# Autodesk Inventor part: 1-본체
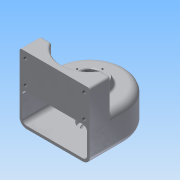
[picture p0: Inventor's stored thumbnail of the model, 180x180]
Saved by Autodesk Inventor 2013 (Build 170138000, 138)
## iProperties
Created: 2015-02
Part Number: 1-본체
Material: 알루미늄 6061
Document SubType Name: Modeling
Designer: Administrator
Density: 2.40731 g/cm^3
Mass: 511.236 g
Surface Area: 706.788 cm^2
Volume: 212.368 cm^3
Author: Administrator
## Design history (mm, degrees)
sketch "스케치1"
  geometry: L1 (-50, 0)-(-50, -50); L2 (-50, -50)-(50, -50); L3 (50, -50)-(50, 0); A1 r 50 centre (0, 0) between (50, 0) and (-50, 0); 1 further point
  constraints: 6 end point, 2 perpendicular, 2 point on circle, 2 tangent, 1 centre point, 1 coincident, 1 horizontal
  dimensions: "d0" = 50 radius of A1; "d2" = 50 distance from line of L2 point (0, 0)
extrude "돌출1" new body sketch "스케치1" distance "d3" = 50; taper "d4" = 0 deg
fillet "모깎기1" dims "d5" = 10
feature "쉘1" dims "d6" = 4
sketch "스케치2"
  geometry: C1 r 25 at (0, 0); A1 r 40 centre (0, 0) between (40, 0) and (-40, 0) reference
  constraints: 1 centre point, 1 coincident
  dimensions: "d7" = 50 diameter of C1
extrude "돌출2" join sketch "스케치2" distance "d9" = 10; taper "d10" = -20 deg
sketch "스케치3"
  geometry: C1 r 20 at (0, 0); A1 r 40 centre (0, 0) between (40, 0) and (-40, 0) reference
  constraints: 1 centre point, 1 coincident
  dimensions: "d11" = 40 diameter of C1
extrude "돌출3" join sketch "스케치3" distance "d13" = 9; taper "d14" = 0 deg
hole "구멍1" diameter "d17" = 20; stored, may be unused: countersink angle "d21" = 90 deg, drill point angle "d23" = 118 deg; dims "d15" = 10, "d16" = 10, "d18" = 6, "d19" = 28, "d20" = 10, "d22" = 8
hole "구멍2" diameter "d26" = 20; stored, may be unused: countersink angle "d30" = 90 deg, drill point angle "d32" = 0 deg; dims "d24" = 10, "d25" = 10, "d27" = 6, "d28" = 28, "d29" = 8, "d31" = 10
node "작업 평면1"
sketch "스케치5"
  geometry: L1 (34.641, -20)-(50, -20); L2 (50, -20)-(50, -50); L3 (50, -50)-(-50, -50); L4 (-50, 0)-(-50, -50) reference; L5 (-50, -50)-(-50, -20); L6 (-34.641, -20)-(-50, -20); L7 (-40, -50)-(40, -50) reference; A1 r 40 centre (0, 0) between (-34.641, -20) and (34.641, -20); 1 further point
  constraints: 10 end point, 2 collinear, 2 perpendicular, 2 point on circle, 2 point on line, 1 centre point, 1 coincident, 1 horizontal, 1 parallel
  dimensions: "d34" = 40 radius of A1; "d36" = 30 distance between parallel lines of L3 L6; "d37" = 100 distance between parallel lines of L4 L2
extrude "돌출4" join sketch "스케치5" stored distance "d38" = 9; taper "d39" = 0 deg
sketch "스케치6"
  geometry: C1 r 14 at (0, 0) reference; C2 r 21.36 at (0, 0) reference; A1 r 18 centre (0, 0) between (0, 18) and (-18, 0); 2 further points
  constraints: 4 point on circle, 2 horizontal alignment, 2 vertical alignment, 1 centre point, 1 coincident
  dimensions: "d40" = 36 diameter of A1
hole "구멍3" sketch "스케치6" at (0, 18), (-18, 0), (0, -18), (18, 0) diameter "d42" = 2.459; stored, may be unused: countersink angle "d46" = 90 deg, drill point angle "d48" = 118 deg; dims "d43" = 6, "d44" = 28, "d45" = 8, "d47" = 9
sketch "스케치8"
  geometry: L1 (-10, 95)-(90, 95) reference; L2 (81.75, 86)-(-1.75, 86); L3 (-1.75, 86)-(-1.75, 53); L4 (-1.75, 53)-(81.75, 53); L5 (81.75, 53)-(81.75, 86); 7 further points
  constraints: 8 end point, 4 coincident, 2 midpoint, 2 parallel, 1 horizontal, 1 perpendicular, 1 vertical alignment
  dimensions: "d49" = 83.5 distance of L2.start L2.end; "d51" = 33 distance of L4.end L2.start; "d52" = 9 distance between parallel lines of L1 L2
hole "구멍4" sketch "스케치8" at (81.75, 86), (81.75, 53), (-1.75, 53), (-1.75, 86) diameter "d53" = 5.134; stored, may be unused: countersink angle "d57" = 90 deg, drill point angle "d59" = 118 deg; dims "d54" = 10, "d55" = 28, "d56" = 8, "d58" = 13
node "작업 평면2"
sketch "스케치9"
  geometry: L1 (-40, 50)-(40, 50) reference; L2 (40, 0)-(-40, 0) reference; 3 further points
  constraints: 1 midpoint, 1 vertical alignment, 1 other
  dimensions: "d60" = 25 distance from line of L2 point (0, 25)
feature "엠보싱1" sketch "스케치9" dims "d0" = 50, "d2" = 50, "d61" = 0.5, "d62" = 0
fillet "모깎기2" dims "d63" = 3
fillet "모깎기3" dims "d64" = 3
fillet "모깎기4" dims "d65" = 3
fillet "모깎기5" dims "d66" = 3
chamfer "모따기1" distance "d67" = 1; stored, may be unused: second distance "d68" = 2, angle "d69" = 45 deg
node "솔리드1"
other parameters: "d33" = 45
